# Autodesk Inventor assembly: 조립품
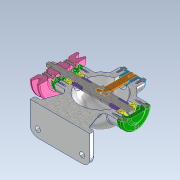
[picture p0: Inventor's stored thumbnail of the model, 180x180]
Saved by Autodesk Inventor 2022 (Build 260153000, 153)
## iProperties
Created: 2024-04
Part Number: 조립품
Document SubType Name: Assembly
Designer: admin
Author: admin
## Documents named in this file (16)
- C:\Users\admin\Desktop\740406V1004\조립품.iam
- C:\Users\admin\Desktop\740406V1004\부품.ipt
- C:\Users\admin\Desktop\740406V1004\뒤커버.ipt
- C:\Users\admin\Desktop\740406V1004\앞커버.ipt
- C:\Users\admin\Desktop\740406V1004\상부커버.ipt
- C:\Users\admin\Desktop\740406V1004\베어링- 6202.ipt
- KS B 2023 - 6202 - 15 x 35 x 11 - 7.8.ipt
- C:\Users\admin\Desktop\740406V1004\칼라.ipt
- C:\Users\admin\Desktop\740406V1004\편심축.ipt
- C:\Users\admin\Desktop\740406V1004\키 4 x 4 x 12.ipt
- C:\Users\admin\Desktop\740406V1004\오일실 15 30 7.ipt
- C:\Users\admin\Desktop\740406V1004\V-벨트풀리.ipt
- C:\Users\admin\Desktop\740406V1004\너트 M8.ipt
- C:\Users\admin\Desktop\740406V1004\볼트 M4 x 16.ipt
- C:\Users\admin\Desktop\740406V1004\볼트 M4 x 12.ipt
- C:\Users\admin\Desktop\740406V1004\슬라이드.ipt
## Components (15 placed, 4 different names)
1. KS B 2023 - 6202 - 15 x 35 x 11 - 7.8:1
2. KS B 2023 - 6202 - 15 x 35 x 11 - 7.8:2
3. V-벨트풀리:1
4. ISO 4762 M4 x 16:1
5. ISO 4762 M4 x 16:2
6. ISO 4762 M4 x 16:3
7. ISO 4762 M4 x 16:4
8. ISO 4762 M4 x 16:5
9. ISO 4762 M4 x 16:6
10. ISO 4762 M4 x 16:7
11. ISO 4762 M4 x 16:8
12. KS B 1021 - 에 따름 ISO 1207 - 미터 A  M 4 x 12:1
13. KS B 1021 - 에 따름 ISO 1207 - 미터 A  M 4 x 12:2
14. KS B 1021 - 에 따름 ISO 1207 - 미터 A  M 4 x 12:3
15. KS B 1021 - 에 따름 ISO 1207 - 미터 A  M 4 x 12:4
